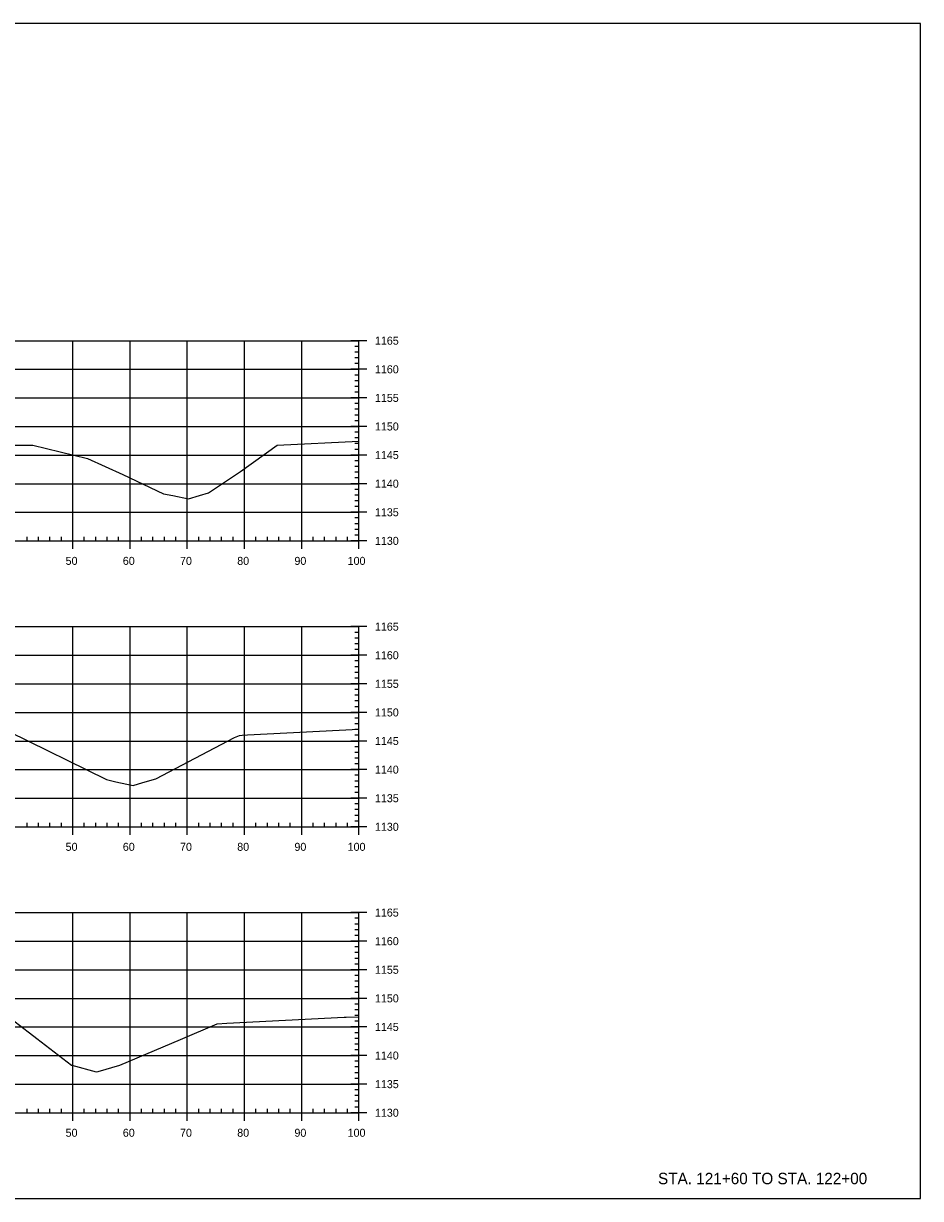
# Model space of a CAD drawing. Extents: x 688474 to 694748, y 765018 to 767373.
# Drawn here: x 690197.7 to 690354.5, y 765298.3 to 765503.8 of the extents above; entities that cross this region are included whole.
import ezdxf

# ---------------------------------------------------------------- set-up
doc = ezdxf.new("R2010")
doc.units = 0
for name, color, linetype in [('60', 7, 'Continuous'), ('R_Exist Surface', 7, 'Continuous'), ('R_Grid', 7, 'Continuous'), ('R_No Plot', 7, 'Continuous')]:
    doc.layers.add(name, color=color, linetype=linetype)

msp = doc.modelspace()

# ---------------------------------------------------------------- linework, layer by layer
at = {"layer": '60'}
for p, q in [((690257.71, 765448.32), (690254.91, 765448.32)), ((690256.31, 765413.32), (690256.31, 765448.32)), ((690256.31, 765447.32), (690255.61, 765447.32)), ((690256.31, 765446.32), (690255.61, 765446.32)), ((690257.71, 765443.32), (690254.91, 765443.32)), ((690256.31, 765445.32), (690255.61, 765445.32)), ((690256.31, 765444.32), (690255.61, 765444.32)), ((690256.31, 765442.32), (690255.61, 765442.32)), ((690256.31, 765441.32), (690255.61, 765441.32)), ((690256.31, 765440.32), (690255.61, 765440.32)), ((690256.31, 765439.32), (690255.61, 765439.32)), ((690257.71, 765438.32), (690254.91, 765438.32)), ((690256.31, 765437.32), (690255.61, 765437.32)), ((690256.31, 765436.32), (690255.61, 765436.32)), ((690256.31, 765435.32), (690255.61, 765435.32)), ((690257.71, 765433.32), (690254.91, 765433.32)), ((690256.31, 765434.32), (690255.61, 765434.32)), ((690256.31, 765432.32), (690255.61, 765432.32)), ((690256.31, 765431.32), (690255.61, 765431.32)), ((690256.31, 765430.32), (690255.61, 765430.32)), ((690256.31, 765429.32), (690255.61, 765429.32)), ((690257.71, 765428.32), (690254.91, 765428.32)), ((690256.31, 765427.32), (690255.61, 765427.32)), ((690256.31, 765426.32), (690255.61, 765426.32)), ((690256.31, 765425.32), (690255.61, 765425.32)), ((690257.71, 765423.32), (690254.91, 765423.32)), ((690256.31, 765424.32), (690255.61, 765424.32)), ((690256.31, 765422.32), (690255.61, 765422.32)), ((690256.31, 765421.32), (690255.61, 765421.32)), ((690256.31, 765420.32), (690255.61, 765420.32)), ((690256.31, 765419.32), (690255.61, 765419.32)), ((690257.71, 765418.32), (690254.91, 765418.32)), ((690256.31, 765417.32), (690255.61, 765417.32)), ((690206.31, 765411.92), (690206.31, 765414.72)), ((690216.31, 765411.92), (690216.31, 765414.72)), ((690226.31, 765411.92), (690226.31, 765414.72)), ((690236.31, 765411.92), (690236.31, 765414.72)), ((690246.31, 765411.92), (690246.31, 765414.72)), ((690256.31, 765416.32), (690255.61, 765416.32)), ((690256.31, 765415.32), (690255.61, 765415.32)), ((690256.31, 765411.92), (690256.31, 765414.72)), ((690056.31, 765413.32), (690256.31, 765413.32)), ((690198.31, 765413.32), (690198.31, 765414.02)), ((690200.31, 765413.32), (690200.31, 765414.02)), ((690202.31, 765413.32), (690202.31, 765414.02)), ((690204.31, 765413.32), (690204.31, 765414.02)), ((690208.31, 765413.32), (690208.31, 765414.02)), ((690210.31, 765413.32), (690210.31, 765414.02)), ((690212.31, 765413.32), (690212.31, 765414.02)), ((690214.31, 765413.32), (690214.31, 765414.02)), ((690218.31, 765413.32), (690218.31, 765414.02)), ((690220.31, 765413.32), (690220.31, 765414.02)), ((690222.31, 765413.32), (690222.31, 765414.02)), ((690224.31, 765413.32), (690224.31, 765414.02)), ((690228.31, 765413.32), (690228.31, 765414.02)), ((690230.31, 765413.32), (690230.31, 765414.02)), ((690232.31, 765413.32), (690232.31, 765414.02)), ((690234.31, 765413.32), (690234.31, 765414.02)), ((690238.31, 765413.32), (690238.31, 765414.02)), ((690240.31, 765413.32), (690240.31, 765414.02)), ((690242.31, 765413.32), (690242.31, 765414.02)), ((690244.31, 765413.32), (690244.31, 765414.02)), ((690248.31, 765413.32), (690248.31, 765414.02)), ((690250.31, 765413.32), (690250.31, 765414.02)), ((690252.31, 765413.32), (690252.31, 765414.02)), ((690254.31, 765413.32), (690254.31, 765414.02)), ((690257.71, 765413.32), (690254.91, 765413.32)), ((690256.31, 765414.32), (690255.61, 765414.32)), ((690257.71, 765398.32), (690254.91, 765398.32)), ((690256.31, 765363.32), (690256.31, 765398.32)), ((690256.31, 765397.32), (690255.61, 765397.32)), ((690256.31, 765396.32), (690255.61, 765396.32)), ((690256.31, 765395.32), (690255.61, 765395.32)), ((690256.31, 765394.32), (690255.61, 765394.32)), ((690257.71, 765393.32), (690254.91, 765393.32)), ((690256.31, 765392.32), (690255.61, 765392.32)), ((690256.31, 765391.32), (690255.61, 765391.32)), ((690256.31, 765390.32), (690255.61, 765390.32)), ((690257.71, 765388.32), (690254.91, 765388.32)), ((690256.31, 765389.32), (690255.61, 765389.32)), ((690256.31, 765387.32), (690255.61, 765387.32)), ((690256.31, 765386.32), (690255.61, 765386.32)), ((690256.31, 765385.32), (690255.61, 765385.32)), ((690256.31, 765384.32), (690255.61, 765384.32)), ((690257.71, 765383.32), (690254.91, 765383.32)), ((690256.31, 765382.32), (690255.61, 765382.32)), ((690256.31, 765381.32), (690255.61, 765381.32)), ((690256.31, 765380.32), (690255.61, 765380.32)), ((690257.71, 765378.32), (690254.91, 765378.32)), ((690256.31, 765379.32), (690255.61, 765379.32)), ((690256.31, 765377.32), (690255.61, 765377.32)), ((690256.31, 765376.32), (690255.61, 765376.32)), ((690256.31, 765375.32), (690255.61, 765375.32)), ((690256.31, 765374.32), (690255.61, 765374.32)), ((690257.71, 765373.32), (690254.91, 765373.32)), ((690256.31, 765372.32), (690255.61, 765372.32)), ((690256.31, 765371.32), (690255.61, 765371.32)), ((690256.31, 765370.32), (690255.61, 765370.32)), ((690256.31, 765369.32), (690255.61, 765369.32)), ((690257.71, 765368.32), (690254.91, 765368.32)), ((690256.31, 765367.32), (690255.61, 765367.32)), ((690256.31, 765366.32), (690255.61, 765366.32)), ((690256.31, 765365.32), (690255.61, 765365.32)), ((690056.31, 765363.32), (690256.31, 765363.32)), ((690198.31, 765363.32), (690198.31, 765364.02)), ((690200.31, 765363.32), (690200.31, 765364.02)), ((690202.31, 765363.32), (690202.31, 765364.02)), ((690204.31, 765363.32), (690204.31, 765364.02)), ((690206.31, 765361.92), (690206.31, 765364.72)), ((690208.31, 765363.32), (690208.31, 765364.02)), ((690210.31, 765363.32), (690210.31, 765364.02)), ((690212.31, 765363.32), (690212.31, 765364.02)), ((690214.31, 765363.32), (690214.31, 765364.02)), ((690216.31, 765361.92), (690216.31, 765364.72)), ((690218.31, 765363.32), (690218.31, 765364.02)), ((690220.31, 765363.32), (690220.31, 765364.02)), ((690222.31, 765363.32), (690222.31, 765364.02)), ((690224.31, 765363.32), (690224.31, 765364.02)), ((690226.31, 765361.92), (690226.31, 765364.72)), ((690228.31, 765363.32), (690228.31, 765364.02)), ((690230.31, 765363.32), (690230.31, 765364.02)), ((690232.31, 765363.32), (690232.31, 765364.02)), ((690234.31, 765363.32), (690234.31, 765364.02)), ((690236.31, 765361.92), (690236.31, 765364.72)), ((690238.31, 765363.32), (690238.31, 765364.02)), ((690240.31, 765363.32), (690240.31, 765364.02)), ((690242.31, 765363.32), (690242.31, 765364.02)), ((690244.31, 765363.32), (690244.31, 765364.02)), ((690246.31, 765361.92), (690246.31, 765364.72)), ((690248.31, 765363.32), (690248.31, 765364.02)), ((690250.31, 765363.32), (690250.31, 765364.02)), ((690252.31, 765363.32), (690252.31, 765364.02)), ((690254.31, 765363.32), (690254.31, 765364.02)), ((690257.71, 765363.32), (690254.91, 765363.32)), ((690256.31, 765364.32), (690255.61, 765364.32)), ((690256.31, 765361.92), (690256.31, 765364.72)), ((690257.71, 765348.32), (690254.91, 765348.32)), ((690256.31, 765347.32), (690255.61, 765347.32)), ((690256.31, 765313.32), (690256.31, 765348.32)), ((690256.31, 765346.32), (690255.61, 765346.32)), ((690256.31, 765345.32), (690255.61, 765345.32)), ((690257.71, 765343.32), (690254.91, 765343.32)), ((690256.31, 765344.32), (690255.61, 765344.32)), ((690256.31, 765342.32), (690255.61, 765342.32)), ((690256.31, 765341.32), (690255.61, 765341.32)), ((690256.31, 765340.32), (690255.61, 765340.32)), ((690256.31, 765339.32), (690255.61, 765339.32)), ((690257.71, 765338.32), (690254.91, 765338.32)), ((690256.31, 765337.32), (690255.61, 765337.32)), ((690256.31, 765336.32), (690255.61, 765336.32)), ((690256.31, 765335.32), (690255.61, 765335.32)), ((690257.71, 765333.32), (690254.91, 765333.32)), ((690256.31, 765334.32), (690255.61, 765334.32)), ((690256.31, 765332.32), (690255.61, 765332.32)), ((690256.31, 765331.32), (690255.61, 765331.32)), ((690256.31, 765330.32), (690255.61, 765330.32)), ((690257.71, 765328.32), (690254.91, 765328.32)), ((690256.31, 765329.32), (690255.61, 765329.32)), ((690256.31, 765327.32), (690255.61, 765327.32)), ((690256.31, 765326.32), (690255.61, 765326.32)), ((690256.31, 765325.32), (690255.61, 765325.32)), ((690256.31, 765324.32), (690255.61, 765324.32)), ((690257.71, 765323.32), (690254.91, 765323.32)), ((690256.31, 765322.32), (690255.61, 765322.32)), ((690256.31, 765321.32), (690255.61, 765321.32)), ((690256.31, 765320.32), (690255.61, 765320.32)), ((690257.71, 765318.32), (690254.91, 765318.32)), ((690256.31, 765319.32), (690255.61, 765319.32)), ((690256.31, 765317.32), (690255.61, 765317.32)), ((690256.31, 765316.32), (690255.61, 765316.32)), ((690198.31, 765313.32), (690198.31, 765314.02)), ((690200.31, 765313.32), (690200.31, 765314.02)), ((690202.31, 765313.32), (690202.31, 765314.02)), ((690204.31, 765313.32), (690204.31, 765314.02)), ((690206.31, 765311.92), (690206.31, 765314.72)), ((690208.31, 765313.32), (690208.31, 765314.02)), ((690210.31, 765313.32), (690210.31, 765314.02)), ((690212.31, 765313.32), (690212.31, 765314.02)), ((690214.31, 765313.32), (690214.31, 765314.02)), ((690216.31, 765311.92), (690216.31, 765314.72)), ((690218.31, 765313.32), (690218.31, 765314.02)), ((690220.31, 765313.32), (690220.31, 765314.02)), ((690222.31, 765313.32), (690222.31, 765314.02)), ((690224.31, 765313.32), (690224.31, 765314.02)), ((690226.31, 765311.92), (690226.31, 765314.72)), ((690228.31, 765313.32), (690228.31, 765314.02)), ((690230.31, 765313.32), (690230.31, 765314.02)), ((690232.31, 765313.32), (690232.31, 765314.02)), ((690234.31, 765313.32), (690234.31, 765314.02)), ((690236.31, 765311.92), (690236.31, 765314.72)), ((690238.31, 765313.32), (690238.31, 765314.02)), ((690240.31, 765313.32), (690240.31, 765314.02)), ((690242.31, 765313.32), (690242.31, 765314.02)), ((690244.31, 765313.32), (690244.31, 765314.02)), ((690246.31, 765311.92), (690246.31, 765314.72)), ((690248.31, 765313.32), (690248.31, 765314.02)), ((690250.31, 765313.32), (690250.31, 765314.02)), ((690252.31, 765313.32), (690252.31, 765314.02)), ((690254.31, 765313.32), (690254.31, 765314.02)), ((690256.31, 765315.32), (690255.61, 765315.32)), ((690256.31, 765314.32), (690255.61, 765314.32)), ((690256.31, 765311.92), (690256.31, 765314.72)), ((690056.31, 765313.32), (690256.31, 765313.32)), ((690257.71, 765313.32), (690254.91, 765313.32))]:
    msp.add_line(p, q, dxfattribs=at)
at = {"layer": 'R_Exist Surface'}
for points in [[(690195.61, 765430.04), (690199.33, 765430.07), (690208.86, 765427.72), (690215.04, 765424.94), (690222.17, 765421.56), (690223.78, 765421.23), (690226.55, 765420.67), (690228.43, 765421.25), (690230, 765421.73), (690235.6, 765425.47), (690242.05, 765430.07), (690256.31, 765430.73)], [(690195.14, 765380), (690212.16, 765371.57), (690213.82, 765371.2), (690216.87, 765370.57), (690218.56, 765371.04), (690220.82, 765371.7), (690234.57, 765378.95), (690235.41, 765379.31), (690235.91, 765379.33), (690236.83, 765379.38), (690256.31, 765380.42)], [(690195.45, 765329.82), (690206.05, 765321.64), (690206.11, 765321.62), (690210.38, 765320.46), (690210.71, 765320.56), (690214.52, 765321.65), (690225.12, 765326.15), (690231.52, 765328.89), (690233.24, 765328.98), (690253.73, 765330.04), (690254.1, 765330.04), (690256.31, 765330.07)]]:
    msp.add_lwpolyline(points, dxfattribs=at)
at = {"layer": 'R_Grid'}
for p, q in [((690056.31, 765448.32), (690256.31, 765448.32)), ((690206.31, 765413.32), (690206.31, 765448.32)), ((690216.31, 765413.32), (690216.31, 765448.32)), ((690226.31, 765413.32), (690226.31, 765448.32)), ((690236.31, 765413.32), (690236.31, 765448.32)), ((690246.31, 765413.32), (690246.31, 765448.32)), ((690256.31, 765413.32), (690256.31, 765448.32)), ((690056.31, 765443.32), (690256.31, 765443.32)), ((690056.31, 765438.32), (690256.31, 765438.32)), ((690056.31, 765433.32), (690256.31, 765433.32)), ((690056.31, 765428.32), (690256.31, 765428.32)), ((690056.31, 765423.32), (690256.31, 765423.32)), ((690056.31, 765418.32), (690256.31, 765418.32)), ((690056.31, 765413.32), (690256.31, 765413.32)), ((690056.31, 765398.32), (690256.31, 765398.32)), ((690206.31, 765363.32), (690206.31, 765398.32)), ((690216.31, 765363.32), (690216.31, 765398.32)), ((690226.31, 765363.32), (690226.31, 765398.32)), ((690236.31, 765363.32), (690236.31, 765398.32)), ((690246.31, 765363.32), (690246.31, 765398.32)), ((690256.31, 765363.32), (690256.31, 765398.32)), ((690056.31, 765393.32), (690256.31, 765393.32)), ((690056.31, 765388.32), (690256.31, 765388.32)), ((690056.31, 765383.32), (690256.31, 765383.32)), ((690056.31, 765378.32), (690256.31, 765378.32)), ((690056.31, 765373.32), (690256.31, 765373.32)), ((690056.31, 765368.32), (690256.31, 765368.32)), ((690056.31, 765363.32), (690256.31, 765363.32)), ((690056.31, 765348.32), (690256.31, 765348.32)), ((690206.31, 765313.32), (690206.31, 765348.32)), ((690216.31, 765313.32), (690216.31, 765348.32)), ((690226.31, 765313.32), (690226.31, 765348.32)), ((690236.31, 765313.32), (690236.31, 765348.32)), ((690246.31, 765313.32), (690246.31, 765348.32)), ((690256.31, 765313.32), (690256.31, 765348.32)), ((690056.31, 765343.32), (690256.31, 765343.32)), ((690056.31, 765338.32), (690256.31, 765338.32)), ((690056.31, 765333.32), (690256.31, 765333.32)), ((690056.31, 765328.32), (690256.31, 765328.32)), ((690056.31, 765323.32), (690256.31, 765323.32)), ((690056.31, 765318.32), (690256.31, 765318.32)), ((690056.31, 765313.32), (690256.31, 765313.32))]:
    msp.add_line(p, q, dxfattribs=at)
at = {"layer": 'R_No Plot'}
msp.add_lwpolyline([(690038.31, 765298.32), (690354.49, 765298.32), (690354.49, 765503.78), (690038.31, 765503.78)], close=True, dxfattribs=at)

# ---------------------------------------------------------------- texts
at = {"layer": '60'}
for s, height, p in [('1165', 1.4, (690259.11, 765447.62)), ('1160', 1.4, (690259.11, 765442.62)), ('1155', 1.4, (690259.11, 765437.62)), ('1150', 1.4, (690259.11, 765432.62)), ('1145', 1.4, (690259.11, 765427.62)), ('1140', 1.4, (690259.11, 765422.62)), ('1135', 1.4, (690259.11, 765417.62)), ('1130', 1.4, (690259.11, 765412.62)), ('50', 1.4, (690205.04, 765409.12)), ('60', 1.4, (690215.04, 765409.12)), ('70', 1.4, (690225.04, 765409.12)), ('80', 1.4, (690235.04, 765409.12)), ('90', 1.4, (690245.04, 765409.12)), ('100', 1.4, (690254.34, 765409.12)), ('1165', 1.4, (690259.11, 765397.62)), ('1160', 1.4, (690259.11, 765392.62)), ('1155', 1.4, (690259.11, 765387.62)), ('1150', 1.4, (690259.11, 765382.62)), ('1145', 1.4, (690259.11, 765377.62)), ('1140', 1.4, (690259.11, 765372.62)), ('1135', 1.4, (690259.11, 765367.62)), ('1130', 1.4, (690259.11, 765362.62)), ('50', 1.4, (690205.04, 765359.12)), ('60', 1.4, (690215.04, 765359.12)), ('70', 1.4, (690225.04, 765359.12)), ('80', 1.4, (690235.04, 765359.12)), ('90', 1.4, (690245.04, 765359.12)), ('100', 1.4, (690254.34, 765359.12)), ('1165', 1.4, (690259.11, 765347.62)), ('1160', 1.4, (690259.11, 765342.62)), ('1155', 1.4, (690259.11, 765337.62)), ('1150', 1.4, (690259.11, 765332.62)), ('1145', 1.4, (690259.11, 765327.62)), ('1140', 1.4, (690259.11, 765322.62)), ('1135', 1.4, (690259.11, 765317.62)), ('1130', 1.4, (690259.11, 765312.62)), ('50', 1.4, (690205.04, 765309.12)), ('60', 1.4, (690215.04, 765309.12)), ('70', 1.4, (690225.04, 765309.12)), ('80', 1.4, (690235.04, 765309.12)), ('90', 1.4, (690245.04, 765309.12)), ('100', 1.4, (690254.34, 765309.12)), ('STA. 121+60 TO STA. 122+00', 2, (690308.6, 765300.82))]:
    msp.add_text(s, height=height, dxfattribs=at).set_placement(p)

doc.saveas('drawing.dxf')
